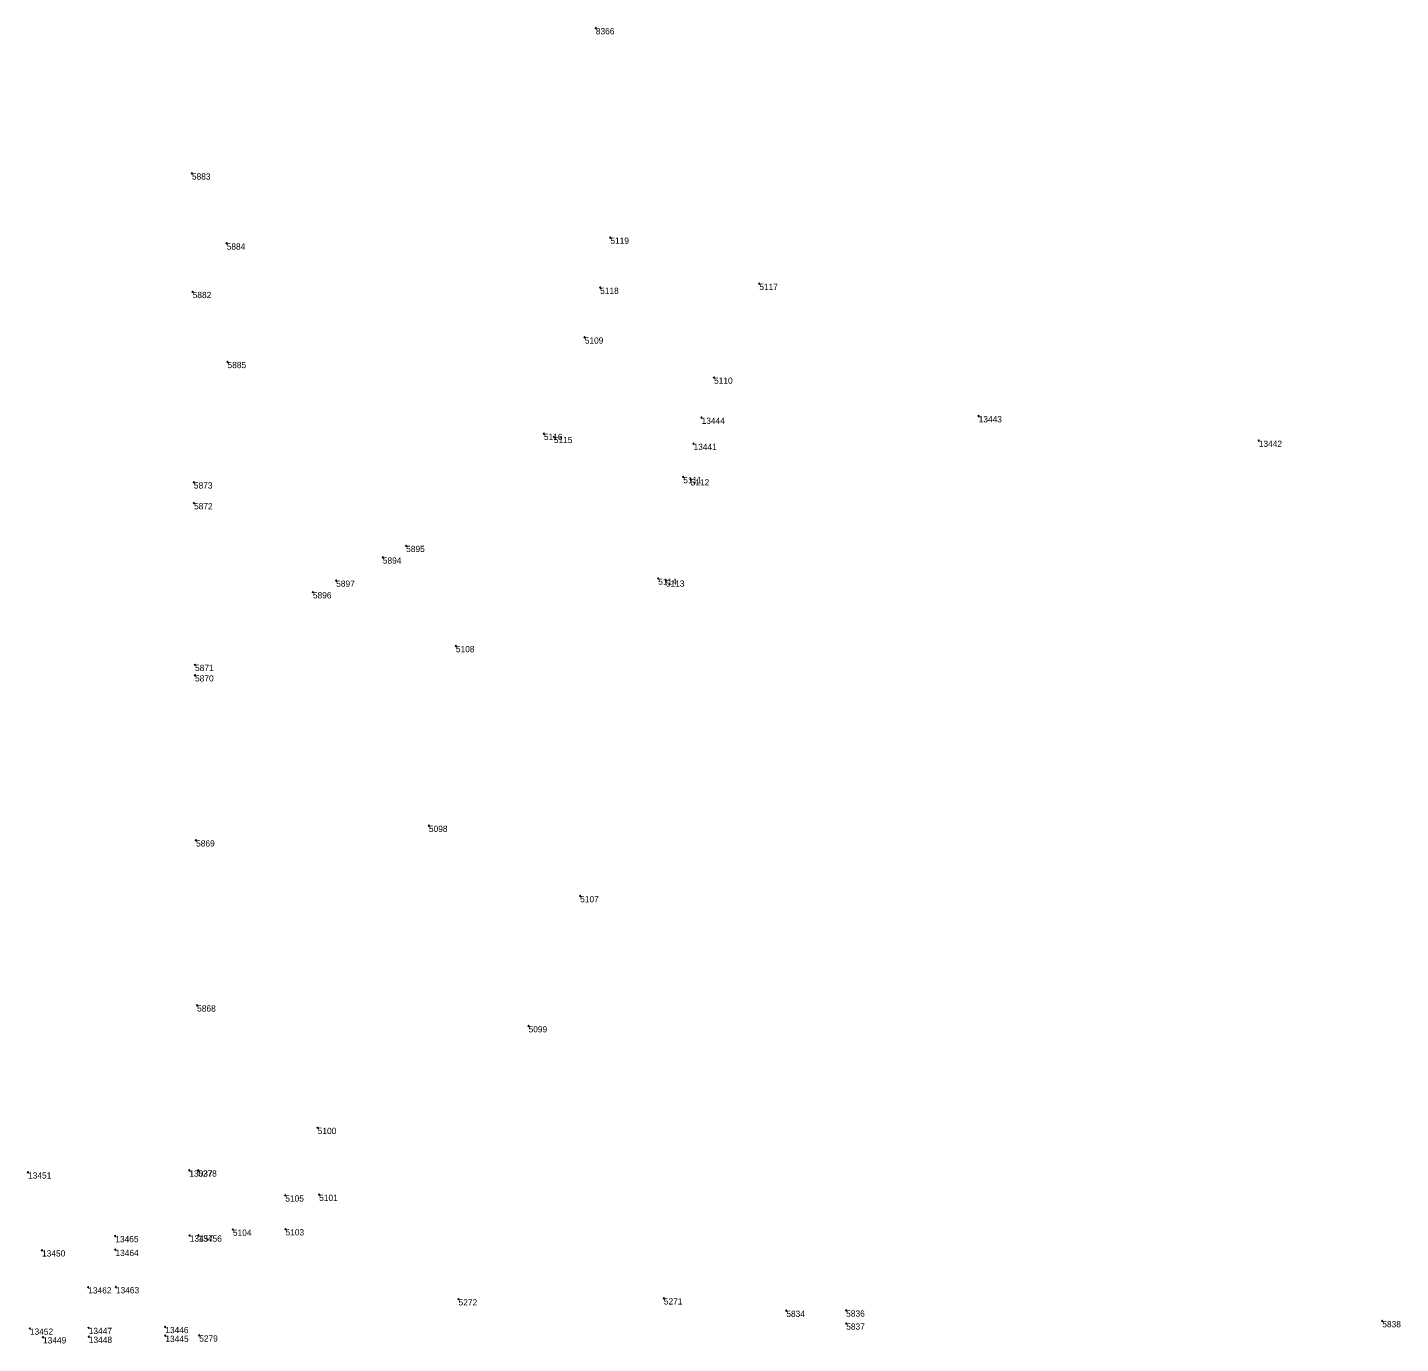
# Model space of a CAD drawing. Extents: x 2145146 to 2158053, y 137507 to 150829.
# Drawn here: x 2150527 to 2153164, y 148302 to 150829 of the extents above; entities that cross this region are included whole.
import ezdxf

# ---------------------------------------------------------------- set-up
doc = ezdxf.new("R2010")
doc.units = 0
doc.layers.add('ALIGN_Cogo Points', color=7, linetype='Continuous')

msp = doc.modelspace()

# ---------------------------------------------------------------- linework, layer by layer
at = {"layer": 'ALIGN_Cogo Points'}
for points in [[(2151618.4, 150828.2), (2151618.4, 150829.4), (2151618.4, 150828.2), (2151617.2, 150828.2), (2151618.4, 150828.2), (2151618.4, 150827), (2151618.4, 150828.2), (2151619.6, 150828.2)], [(2150842.7, 150549.2), (2150842.7, 150550.4), (2150842.7, 150549.2), (2150841.5, 150549.2), (2150842.7, 150549.2), (2150842.7, 150548), (2150842.7, 150549.2), (2150843.9, 150549.2)], [(2150909.5, 150414.7), (2150909.5, 150415.9), (2150909.5, 150414.7), (2150908.3, 150414.7), (2150909.5, 150414.7), (2150909.5, 150413.5), (2150909.5, 150414.7), (2150910.7, 150414.7)], [(2151646.3, 150425.9), (2151646.3, 150427.1), (2151646.3, 150425.9), (2151645.1, 150425.9), (2151646.3, 150425.9), (2151646.3, 150424.7), (2151646.3, 150425.9), (2151647.5, 150425.9)], [(2151932.3, 150337.2), (2151932.3, 150338.4), (2151932.3, 150337.2), (2151931.1, 150337.2), (2151932.3, 150337.2), (2151932.3, 150336), (2151932.3, 150337.2), (2151933.5, 150337.2)], [(2150844.1, 150321.6), (2150844.1, 150322.8), (2150844.1, 150321.6), (2150842.9, 150321.6), (2150844.1, 150321.6), (2150844.1, 150320.4), (2150844.1, 150321.6), (2150845.3, 150321.6)], [(2151626.7, 150329.7), (2151626.7, 150330.9), (2151626.7, 150329.7), (2151625.5, 150329.7), (2151626.7, 150329.7), (2151626.7, 150328.5), (2151626.7, 150329.7), (2151627.9, 150329.7)], [(2151597.1, 150234.1), (2151597.1, 150235.3), (2151597.1, 150234.1), (2151595.9, 150234.1), (2151597.1, 150234.1), (2151597.1, 150232.9), (2151597.1, 150234.1), (2151598.3, 150234.1)], [(2150911, 150187.1), (2150911, 150188.3), (2150911, 150187.1), (2150909.8, 150187.1), (2150911, 150187.1), (2150911, 150185.9), (2150911, 150187.1), (2150912.2, 150187.1)], [(2151845.4, 150157.1), (2151845.4, 150158.3), (2151845.4, 150157.1), (2151844.2, 150157.1), (2151845.4, 150157.1), (2151845.4, 150155.9), (2151845.4, 150157.1), (2151846.6, 150157.1)], [(2151821.5, 150080.1), (2151821.5, 150081.3), (2151821.5, 150080.1), (2151820.3, 150080.1), (2151821.5, 150080.1), (2151821.5, 150078.9), (2151821.5, 150080.1), (2151822.7, 150080.1)], [(2152353.6, 150083), (2152353.6, 150084.2), (2152353.6, 150083), (2152352.4, 150083), (2152353.6, 150083), (2152353.6, 150081.8), (2152353.6, 150083), (2152354.8, 150083)], [(2151518.7, 150049), (2151518.7, 150050.2), (2151518.7, 150049), (2151517.5, 150049), (2151518.7, 150049), (2151518.7, 150047.8), (2151518.7, 150049), (2151519.9, 150049)], [(2151537.8, 150043.1), (2151537.8, 150044.3), (2151537.8, 150043.1), (2151536.6, 150043.1), (2151537.8, 150043.1), (2151537.8, 150041.9), (2151537.8, 150043.1), (2151539, 150043.1)], [(2151806, 150030), (2151806, 150031.2), (2151806, 150030), (2151804.8, 150030), (2151806, 150030), (2151806, 150028.8), (2151806, 150030), (2151807.2, 150030)], [(2152891.6, 150035.8), (2152891.6, 150037), (2152891.6, 150035.8), (2152890.4, 150035.8), (2152891.6, 150035.8), (2152891.6, 150034.6), (2152891.6, 150035.8), (2152892.8, 150035.8)], [(2151786.2, 149966.1), (2151786.2, 149967.3), (2151786.2, 149966.1), (2151785, 149966.1), (2151786.2, 149966.1), (2151786.2, 149964.9), (2151786.2, 149966.1), (2151787.4, 149966.1)], [(2150846.4, 149955.8), (2150846.4, 149957), (2150846.4, 149955.8), (2150845.2, 149955.8), (2150846.4, 149955.8), (2150846.4, 149954.6), (2150846.4, 149955.8), (2150847.6, 149955.8)], [(2151800.5, 149961.7), (2151800.5, 149962.9), (2151800.5, 149961.7), (2151799.3, 149961.7), (2151800.5, 149961.7), (2151800.5, 149960.5), (2151800.5, 149961.7), (2151801.7, 149961.7)], [(2150846.7, 149915.8), (2150846.7, 149917), (2150846.7, 149915.8), (2150845.5, 149915.8), (2150846.7, 149915.8), (2150846.7, 149914.6), (2150846.7, 149915.8), (2150847.9, 149915.8)], [(2151254.1, 149833.8), (2151254.1, 149835), (2151254.1, 149833.8), (2151252.9, 149833.8), (2151254.1, 149833.8), (2151254.1, 149832.6), (2151254.1, 149833.8), (2151255.3, 149833.8)], [(2151209.3, 149811.6), (2151209.3, 149812.8), (2151209.3, 149811.6), (2151208.1, 149811.6), (2151209.3, 149811.6), (2151209.3, 149810.4), (2151209.3, 149811.6), (2151210.5, 149811.6)], [(2151119.7, 149767.1), (2151119.7, 149768.3), (2151119.7, 149767.1), (2151118.5, 149767.1), (2151119.7, 149767.1), (2151119.7, 149765.9), (2151119.7, 149767.1), (2151120.9, 149767.1)], [(2151738.2, 149771), (2151738.2, 149772.2), (2151738.2, 149771), (2151737, 149771), (2151738.2, 149771), (2151738.2, 149769.8), (2151738.2, 149771), (2151739.4, 149771)], [(2151752.8, 149767.4), (2151752.8, 149768.6), (2151752.8, 149767.4), (2151751.6, 149767.4), (2151752.8, 149767.4), (2151752.8, 149766.2), (2151752.8, 149767.4), (2151754, 149767.4)], [(2151075, 149744.8), (2151075, 149746), (2151075, 149744.8), (2151073.8, 149744.8), (2151075, 149744.8), (2151075, 149743.6), (2151075, 149744.8), (2151076.2, 149744.8)], [(2151349.6, 149641.5), (2151349.6, 149642.7), (2151349.6, 149641.5), (2151348.4, 149641.5), (2151349.6, 149641.5), (2151349.6, 149640.3), (2151349.6, 149641.5), (2151350.8, 149641.5)], [(2150848.6, 149605.3), (2150848.6, 149606.5), (2150848.6, 149605.3), (2150847.4, 149605.3), (2150848.6, 149605.3), (2150848.6, 149604.1), (2150848.6, 149605.3), (2150849.8, 149605.3)], [(2150848.7, 149585.3), (2150848.7, 149586.5), (2150848.7, 149585.3), (2150847.5, 149585.3), (2150848.7, 149585.3), (2150848.7, 149584.1), (2150848.7, 149585.3), (2150849.9, 149585.3)], [(2151297.8, 149296.3), (2151297.8, 149297.5), (2151297.8, 149296.3), (2151296.6, 149296.3), (2151297.8, 149296.3), (2151297.8, 149295.1), (2151297.8, 149296.3), (2151299, 149296.3)], [(2150850.7, 149268.3), (2150850.7, 149269.5), (2150850.7, 149268.3), (2150849.5, 149268.3), (2150850.7, 149268.3), (2150850.7, 149267.1), (2150850.7, 149268.3), (2150851.9, 149268.3)], [(2151588.3, 149161.2), (2151588.3, 149162.4), (2151588.3, 149161.2), (2151587.1, 149161.2), (2151588.3, 149161.2), (2151588.3, 149160), (2151588.3, 149161.2), (2151589.5, 149161.2)], [(2150852.7, 148951.3), (2150852.7, 148952.5), (2150852.7, 148951.3), (2150851.5, 148951.3), (2150852.7, 148951.3), (2150852.7, 148950.1), (2150852.7, 148951.3), (2150853.9, 148951.3)], [(2151489.2, 148911.3), (2151489.2, 148912.5), (2151489.2, 148911.3), (2151488, 148911.3), (2151489.2, 148911.3), (2151489.2, 148910.1), (2151489.2, 148911.3), (2151490.4, 148911.3)], [(2151084.3, 148716), (2151084.3, 148717.2), (2151084.3, 148716), (2151083.1, 148716), (2151084.3, 148716), (2151084.3, 148714.8), (2151084.3, 148716), (2151085.5, 148716)], [(2150528, 148630.5), (2150528, 148631.7), (2150528, 148630.5), (2150526.8, 148630.5), (2150528, 148630.5), (2150528, 148629.3), (2150528, 148630.5), (2150529.2, 148630.5)], [(2150837.7, 148634.1), (2150837.7, 148635.3), (2150837.7, 148634.1), (2150836.5, 148634.1), (2150837.7, 148634.1), (2150837.7, 148632.9), (2150837.7, 148634.1), (2150838.9, 148634.1)], [(2150854.7, 148634.3), (2150854.7, 148635.5), (2150854.7, 148634.3), (2150853.5, 148634.3), (2150854.7, 148634.3), (2150854.7, 148633.1), (2150854.7, 148634.3), (2150855.9, 148634.3)], [(2151022, 148586.3), (2151022, 148587.5), (2151022, 148586.3), (2151020.8, 148586.3), (2151022, 148586.3), (2151022, 148585.1), (2151022, 148586.3), (2151023.2, 148586.3)], [(2151087, 148587.6), (2151087, 148588.8), (2151087, 148587.6), (2151085.8, 148587.6), (2151087, 148587.6), (2151087, 148586.4), (2151087, 148587.6), (2151088.2, 148587.6)], [(2150921.4, 148520.6), (2150921.4, 148521.8), (2150921.4, 148520.6), (2150920.2, 148520.6), (2150921.4, 148520.6), (2150921.4, 148519.4), (2150921.4, 148520.6), (2150922.6, 148520.6)], [(2151022.4, 148521.3), (2151022.4, 148522.5), (2151022.4, 148521.3), (2151021.2, 148521.3), (2151022.4, 148521.3), (2151022.4, 148520.1), (2151022.4, 148521.3), (2151023.6, 148521.3)], [(2150695.5, 148508.3), (2150695.5, 148509.5), (2150695.5, 148508.3), (2150694.3, 148508.3), (2150695.5, 148508.3), (2150695.5, 148507.1), (2150695.5, 148508.3), (2150696.7, 148508.3)], [(2150838.5, 148509.2), (2150838.5, 148510.4), (2150838.5, 148509.2), (2150837.3, 148509.2), (2150838.5, 148509.2), (2150838.5, 148508), (2150838.5, 148509.2), (2150839.7, 148509.2)], [(2150855.5, 148509.3), (2150855.5, 148510.5), (2150855.5, 148509.3), (2150854.3, 148509.3), (2150855.5, 148509.3), (2150855.5, 148508.1), (2150855.5, 148509.3), (2150856.7, 148509.3)], [(2150554.8, 148480.8), (2150554.8, 148482), (2150554.8, 148480.8), (2150553.6, 148480.8), (2150554.8, 148480.8), (2150554.8, 148479.6), (2150554.8, 148480.8), (2150556, 148480.8)], [(2150695.8, 148481.7), (2150695.8, 148482.9), (2150695.8, 148481.7), (2150694.6, 148481.7), (2150695.8, 148481.7), (2150695.8, 148480.5), (2150695.8, 148481.7), (2150697, 148481.7)], [(2150643.6, 148409.8), (2150643.6, 148411), (2150643.6, 148409.8), (2150642.4, 148409.8), (2150643.6, 148409.8), (2150643.6, 148408.6), (2150643.6, 148409.8), (2150644.8, 148409.8)], [(2150696.7, 148410.2), (2150696.7, 148411.4), (2150696.7, 148410.2), (2150695.5, 148410.2), (2150696.7, 148410.2), (2150696.7, 148409), (2150696.7, 148410.2), (2150697.9, 148410.2)], [(2151354.8, 148386.8), (2151354.8, 148388), (2151354.8, 148386.8), (2151353.6, 148386.8), (2151354.8, 148386.8), (2151354.8, 148385.6), (2151354.8, 148386.8), (2151356, 148386.8)], [(2151749, 148388.6), (2151749, 148389.8), (2151749, 148388.6), (2151747.8, 148388.6), (2151749, 148388.6), (2151749, 148387.4), (2151749, 148388.6), (2151750.2, 148388.6)], [(2151984.2, 148364.7), (2151984.2, 148365.9), (2151984.2, 148364.7), (2151983, 148364.7), (2151984.2, 148364.7), (2151984.2, 148363.5), (2151984.2, 148364.7), (2151985.4, 148364.7)], [(2152099.2, 148365.2), (2152099.2, 148366.4), (2152099.2, 148365.2), (2152098, 148365.2), (2152099.2, 148365.2), (2152099.2, 148364), (2152099.2, 148365.2), (2152100.4, 148365.2)], [(2150531.5, 148330.5), (2150531.5, 148331.7), (2150531.5, 148330.5), (2150530.3, 148330.5), (2150531.5, 148330.5), (2150531.5, 148329.3), (2150531.5, 148330.5), (2150532.7, 148330.5)], [(2150644.5, 148331.8), (2150644.5, 148333), (2150644.5, 148331.8), (2150643.3, 148331.8), (2150644.5, 148331.8), (2150644.5, 148330.6), (2150644.5, 148331.8), (2150645.7, 148331.8)], [(2150791.5, 148333.6), (2150791.5, 148334.8), (2150791.5, 148333.6), (2150790.3, 148333.6), (2150791.5, 148333.6), (2150791.5, 148332.4), (2150791.5, 148333.6), (2150792.7, 148333.6)], [(2152099.3, 148340.2), (2152099.3, 148341.4), (2152099.3, 148340.2), (2152098.1, 148340.2), (2152099.3, 148340.2), (2152099.3, 148339), (2152099.3, 148340.2), (2152100.5, 148340.2)], [(2153128.8, 148344.8), (2153128.8, 148346), (2153128.8, 148344.8), (2153127.6, 148344.8), (2153128.8, 148344.8), (2153128.8, 148343.6), (2153128.8, 148344.8), (2153130, 148344.8)], [(2150556.7, 148313.8), (2150556.7, 148315), (2150556.7, 148313.8), (2150555.5, 148313.8), (2150556.7, 148313.8), (2150556.7, 148312.6), (2150556.7, 148313.8), (2150557.9, 148313.8)], [(2150644.7, 148314.8), (2150644.7, 148316), (2150644.7, 148314.8), (2150643.5, 148314.8), (2150644.7, 148314.8), (2150644.7, 148313.6), (2150644.7, 148314.8), (2150645.9, 148314.8)], [(2150791.7, 148316.6), (2150791.7, 148317.8), (2150791.7, 148316.6), (2150790.5, 148316.6), (2150791.7, 148316.6), (2150791.7, 148315.4), (2150791.7, 148316.6), (2150792.9, 148316.6)], [(2150856.7, 148317.3), (2150856.7, 148318.5), (2150856.7, 148317.3), (2150855.5, 148317.3), (2150856.7, 148317.3), (2150856.7, 148316.1), (2150856.7, 148317.3), (2150857.9, 148317.3)]]:
    msp.add_lwpolyline(points, dxfattribs=at)

# ---------------------------------------------------------------- texts
for s, p in [('8366', (2151618.4, 150816.2)), ('5883', (2150842.7, 150537.2)), ('5884', (2150909.5, 150402.7)), ('5119', (2151646.3, 150413.9)), ('5117', (2151932.3, 150325.2)), ('5882', (2150844.1, 150309.6)), ('5118', (2151626.7, 150317.7)), ('5109', (2151597.1, 150222.1)), ('5885', (2150911, 150175.1)), ('5110', (2151845.4, 150145.1)), ('13444', (2151821.5, 150068.1)), ('13443', (2152353.6, 150071)), ('5116', (2151518.7, 150037)), ('5115', (2151537.8, 150031.1)), ('13441', (2151806, 150018)), ('13442', (2152891.6, 150023.8)), ('5111', (2151786.2, 149954.1)), ('5873', (2150846.4, 149943.8)), ('5112', (2151800.5, 149949.7)), ('5872', (2150846.7, 149903.8)), ('5895', (2151254.1, 149821.8)), ('5894', (2151209.3, 149799.6)), ('5897', (2151119.7, 149755.1)), ('5114', (2151738.2, 149759)), ('5113', (2151752.8, 149755.4)), ('5896', (2151075, 149732.8)), ('5108', (2151349.6, 149629.5)), ('5871', (2150848.6, 149593.3)), ('5870', (2150848.7, 149573.3)), ('5098', (2151297.8, 149284.3)), ('5869', (2150850.7, 149256.3)), ('5107', (2151588.3, 149149.2)), ('5868', (2150852.7, 148939.3)), ('5099', (2151489.2, 148899.3)), ('5100', (2151084.3, 148704)), ('13451', (2150528, 148618.5)), ('13037', (2150837.7, 148622.1)), ('5278', (2150854.7, 148622.3)), ('5105', (2151022, 148574.3)), ('5101', (2151087, 148575.6)), ('5104', (2150921.4, 148508.6)), ('5103', (2151022.4, 148509.3)), ('13465', (2150695.5, 148496.3)), ('13457', (2150838.5, 148497.2)), ('13456', (2150855.5, 148497.3)), ('13450', (2150554.8, 148468.8)), ('13464', (2150695.8, 148469.7)), ('13462', (2150643.6, 148397.8)), ('13463', (2150696.7, 148398.2)), ('5272', (2151354.8, 148374.8)), ('5271', (2151749, 148376.6)), ('5834', (2151984.2, 148352.7)), ('5836', (2152099.2, 148353.2)), ('13452', (2150531.5, 148318.5)), ('13447', (2150644.5, 148319.8)), ('13446', (2150791.5, 148321.6)), ('5837', (2152099.3, 148328.2)), ('5838', (2153128.8, 148332.8)), ('13449', (2150556.7, 148301.8)), ('13448', (2150644.7, 148302.8)), ('13445', (2150791.7, 148304.6)), ('5279', (2150856.7, 148305.3))]:
    msp.add_text(s, height=12, dxfattribs=at).set_placement(p)

doc.saveas('drawing.dxf')
